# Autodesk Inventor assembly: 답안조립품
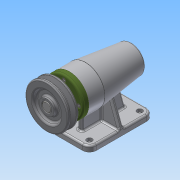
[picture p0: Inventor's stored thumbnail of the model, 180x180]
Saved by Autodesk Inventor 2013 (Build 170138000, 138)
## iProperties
Created: 2018-09
Part Number: 답안조립품
Document SubType Name: Assembly
Designer: Administrator
Author: Administrator
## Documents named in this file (12)
- C:\Users\Administrator\Desktop\480908V1003\답안조립품.iam
- C:\Users\Administrator\Desktop\480908V1003\본체.ipt
- C:\Users\Administrator\Desktop\480908V1003\V벨트풀리.ipt
- C:\Users\Administrator\Desktop\480908V1003\멈춤나사 M3.ipt
- C:\Users\Administrator\Desktop\480908V1003\베어링 6004.ipt
- C:\Users\Administrator\Desktop\480908V1003\베어링 51202.ipt
- C:\Users\Administrator\Desktop\480908V1003\볼트 M4.ipt
- C:\Users\Administrator\Desktop\480908V1003\어댑터슬리브.ipt
- C:\Users\Administrator\Desktop\480908V1003\오일 실.ipt
- C:\Users\Administrator\Desktop\480908V1003\축.ipt
- C:\Users\Administrator\Desktop\480908V1003\커버.ipt
- C:\Users\Administrator\Desktop\480908V1003\키 5 x 5 x 16.ipt
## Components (1 placed, 1 different names)
1. V벨트풀리:2
